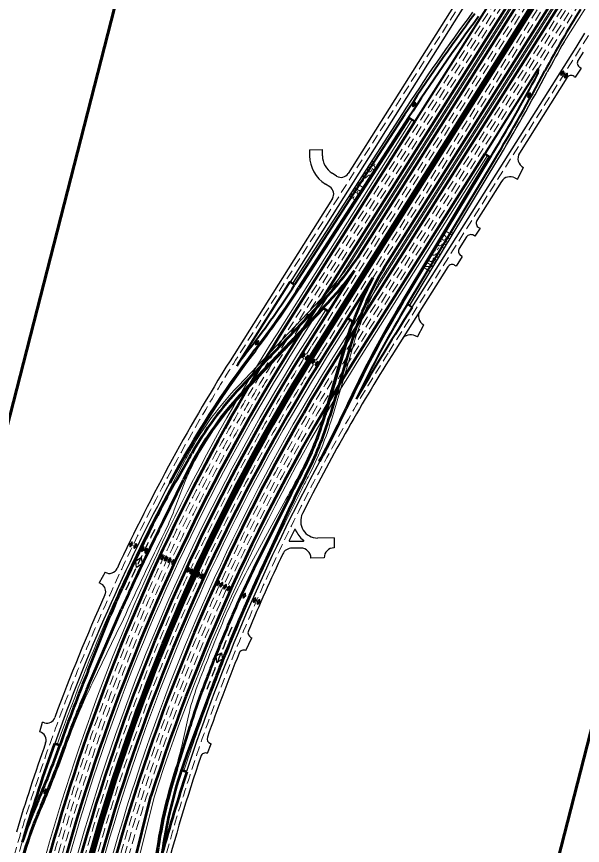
# Model space of a CAD drawing. Extents: x 2329387 to 2347382, y 6951580 to 6987999.
# Drawn here: x 2330678 to 2332354, y 6976295 to 6978752 of the extents above; entities that cross this region are included whole.
import ezdxf

# ---------------------------------------------------------------- set-up
doc = ezdxf.new("R2010")
doc.units = 0
doc.header["$LTSCALE"] = 9.6
doc.linetypes.add('MEDIUM_DASHED', pattern=[4.5, 3, -1.5])
for name, color, linetype, lineweight in [('26', 7, 'Continuous', 53), ('27', 7, 'Continuous', 40), ('28', 7, 'Continuous', 25), ('30', 7, 'Continuous', 13), ('31', 7, 'Continuous', 53), ('41', 7, 'Continuous', 35), ('50', 7, 'MEDIUM_DASHED', 13), ('62', 7, 'Continuous', 60), ('8', 7, 'Continuous', 25)]:
    doc.layers.add(name, color=color, linetype=linetype, lineweight=lineweight)
doc.layers.add('40', color=7, linetype='Continuous')

msp = doc.modelspace()

# ---------------------------------------------------------------- linework, layer by layer
at = {"layer": '26'}
for p, q in [((2332311.656, 6979070.557), (2331498.365, 6977780.703)), ((2332421.635, 6979001.242), (2331638.131, 6977758.629)), ((2331857.752, 6978440.676), (2331457.762, 6977806.304)), ((2332064.627, 6978345.043), (2331678.734, 6977733.028)), ((2331002.95, 6976149.883), (2331075.736, 6976441.452))]:
    msp.add_line(p, q, dxfattribs=at)
at = {"layer": '26', "lineweight": 13}
for p, q in [((2332320.115, 6979065.224), (2331506.824, 6977775.369)), ((2332413.166, 6979006.559), (2331629.672, 6977763.963)), ((2332480.843, 6978963.9), (2332299.878, 6978676.896)), ((2331849.293, 6978446.009), (2331449.303, 6977811.638)), ((2332073.086, 6978339.709), (2331687.192, 6977727.694)), ((2331012.618, 6976147.33), (2331085.256, 6976438.392))]:
    msp.add_line(p, q, dxfattribs=at)
for centre, radius, end in [((2336379.635, 6974702.917), 5828.578, 173.81243), ((2336379.635, 6974702.917), 5760.578, 175.11878), ((2336484.72, 6974702.711), 5739.578, 175.08526), ((2336484.72, 6974702.711), 5671.578, 162.17978)]:
    msp.add_arc(centre, radius, 147.76736, end, dxfattribs=at)
at = {"layer": '26'}
for centre, radius, end in [((2336379.635, 6974702.917), 5818.578, 172.95165), ((2336379.635, 6974702.917), 5770.578, 175.12833), ((2336484.72, 6974702.711), 5729.578, 175.07558), ((2336484.72, 6974702.711), 5681.578, 162.17978)]:
    msp.add_arc(centre, radius, 147.76736, end, dxfattribs=at)
at = {"layer": '27'}
for p, q in [((2332110.036, 6978840.79), (2331857.752, 6978440.676)), ((2332223.361, 6978596.79), (2332064.627, 6978345.043)), ((2332223.361, 6978596.79), (2332222.374, 6978582.1)), ((2331827.389, 6978460.014), (2331501.466, 6977956.236)), ((2331839.144, 6978452.409), (2331513.22, 6977948.632)), ((2331857.752, 6978440.676), (2331839.143, 6978452.41)), ((2331823.332, 6977906.104), (2332081.553, 6978334.383)), ((2332081.547, 6978334.374), (2332064.627, 6978345.043)), ((2331835.322, 6977898.876), (2332093.542, 6978327.154)), ((2331487.041, 6977965.235), (2331343.214, 6977737.129)), ((2331501.421, 6977956.168), (2331487.041, 6977965.235)), ((2331835.322, 6977898.876), (2331849.702, 6977889.808)), ((2331849.702, 6977889.808), (2331826.155, 6977852.463))]:
    msp.add_line(p, q, dxfattribs=at)
at = {"layer": '27', "lineweight": 25}
for p, q in [((2331820.672, 6978464.359), (2331494.654, 6977960.435)), ((2331842.502, 6978450.236), (2331516.579, 6977946.459)), ((2331819.907, 6977908.17), (2332078.163, 6978336.508)), ((2331842.09, 6977894.608), (2332100.393, 6978323.023)), ((2331577.072, 6977433.381), (2331573.552, 6977435.281)), ((2331130.648, 6977370.742), (2331134.18, 6977368.863))]:
    msp.add_line(p, q, dxfattribs=at)
for centre, radius, start, end in [((2336637.99, 6975347.75), 5737.578, 143.44999, 147.09877), ((2334771.719, 6977244.678), 2856.789, 149.91143, 151.98091), ((2327184.689, 6981282.018), 5737.578, 328.95434, 331.98091), ((2329096.165, 6979512.368), 2882.789, 322.59517, 327.09877), ((2334639.165, 6976208.364), 3292.044, 148.91312, 155.15778), ((2333647.533, 6976031.977), 2846.789, 142.59517, 151.99089), ((2329068.37, 6978787.417), 2846.789, 331.64269, 335.15778)]:
    msp.add_arc(centre, radius, start, end, dxfattribs=at)
at = {"layer": '27'}
for centre, radius, start, end in [((2336637.99, 6975347.75), 5729.578, 143.44999, 147.09877), ((2336637.99, 6975347.75), 5715.578, 143.44999, 147.09877), ((2334771.719, 6977244.678), 2864.789, 147.76736, 151.98091), ((2327184.689, 6981282.018), 5715.578, 328.95434, 331.81118), ((2327184.689, 6981282.018), 5729.578, 328.95434, 331.98091), ((2329096.165, 6979512.368), 2864.789, 322.59517, 327.09878), ((2329096.165, 6979512.368), 2878.789, 322.59517, 327.09877), ((2334639.165, 6976208.364), 3288.044, 148.91312, 155.15778), ((2334639.165, 6976208.364), 3274.044, 148.91312, 154.49671), ((2338308.575, 6973765.105), 7663.437, 147.76735, 149.81661), ((2333647.533, 6976031.977), 2864.789, 142.59517, 144.00072), ((2333647.533, 6976031.977), 2850.789, 142.59517, 151.99089), ((2336205.029, 6974671.61), 5747.578, 147.76736, 148.01803), ((2329068.37, 6978787.417), 2850.789, 331.64269, 335.15778)]:
    msp.add_arc(centre, radius, start, end, dxfattribs=at)
at = {"layer": '28'}
for p, q in [((2332268.48, 6979251.445), (2331660.223, 6978286.769)), ((2332225.857, 6979135.099), (2331487.887, 6977964.701)), ((2332360.201, 6978702.494), (2332334.063, 6978659.865)), ((2332334.063, 6978659.865), (2331848.856, 6977890.342)), ((2332356.056, 6978645.998), (2332341.081, 6978622.248)), ((2332308.053, 6978569.867), (2332167.564, 6978347.055)), ((2332329.047, 6978574.357), (2332332.909, 6978571.789)), ((2331545.827, 6978357.015), (2331583.827, 6978357.205)), ((2331545.827, 6978357.015), (2331545.917, 6978339.029)), ((2331583.92, 6978338.547), (2331583.827, 6978357.205)), ((2331625.742, 6978278.955), (2331612.847, 6978287.086)), ((2332161.923, 6978269.542), (2332179.767, 6978304.102)), ((2332114.627, 6978263.098), (2332041.55, 6978147.201)), ((2332153.767, 6978273.753), (2332161.923, 6978269.542)), ((2331605.474, 6978246.812), (2331592.58, 6978254.942)), ((2331613.288, 6978212.33), (2331322.066, 6977750.463)), ((2332050.692, 6978124.201), (2332035.634, 6978100.319)), ((2332050.692, 6978124.201), (2332047.522, 6978125.789)), ((2332010.796, 6978098.425), (2331989.138, 6978064.077)), ((2332035.634, 6978100.319), (2332031.881, 6978102.854)), ((2331997.916, 6978040.5), (2331993.218, 6978043.793)), ((2331955.002, 6978009.939), (2331789.547, 6977747.531)), ((2331865.02, 6977802.141), (2331883.823, 6977837.753)), ((2331865.02, 6977802.141), (2331858.956, 6977805.343)), ((2331618.535, 6977206.483), (2331569.576, 6977206.193)), ((2331618.535, 6977206.483), (2331618.708, 6977177.234)), ((2331526.484, 6977196.296), (2331487.168, 6977196.194)), ((2331519.723, 6977176.278), (2331493.255, 6977176.209)), ((2331588.788, 6977147.607), (2331549.8, 6977146.362)), ((2330940.545, 6977104.625), (2330922.891, 6977073.251)), ((2330929.109, 6977069.752), (2330922.891, 6977073.251)), ((2331357.18, 6976872.848), (2331374.184, 6976910.605)), ((2331372.097, 6976911.544), (2331374.184, 6976910.605)), ((2330746.713, 6976631.731), (2330754.247, 6976660.161)), ((2330760.898, 6976658.378), (2330754.247, 6976660.161)), ((2331243.387, 6976568.227), (2331254.398, 6976595.868)), ((2331251.762, 6976596.918), (2331254.398, 6976595.868))]:
    msp.add_line(p, q, dxfattribs=at)
for points in [[(2332346.54, 6978601.104), (2332350.144, 6978599.122), (2332332.909, 6978571.789)], [(2331997.916, 6978040.5), (2331979.8, 6978011.769), (2331976.3, 6978014.222)]]:
    msp.add_lwpolyline(points, dxfattribs=at)
for centre, radius, start, end in [((2332353.769, 6978614.247), 15, 147.76735, 241.1848), ((2332320.742, 6978561.866), 15, 56.37914, 147.76735), ((2331645.916, 6978339.531), 100, 180.28727, 237.76736), ((2331645.916, 6978339.531), 62, 180.28727, 237.76652), ((2332192.941, 6978331.055), 30, 147.76735, 243.95256), ((2331639.076, 6978300.103), 25, 237.76736, 327.76736), ((2332140.003, 6978247.097), 30, 62.69027, 147.76736), ((2331592.14, 6978225.664), 25, 327.76736, 57.76736), ((2332054.239, 6978139.201), 15, 147.76735, 243.3983), ((2332023.484, 6978090.425), 15, 55.95931, 147.76735), ((2332001.827, 6978056.077), 15, 147.76736, 234.97513), ((2331967.691, 6978001.938), 15, 54.97512, 147.76735), ((2331898.424, 6977863.96), 30, 147.76735, 240.87564), ((2331844.949, 6977778.813), 30, 62.16612, 148.16102), ((2336205.029, 6974671.61), 5772.578, 147.76736, 154.9494), ((2336512.636, 6974769.483), 5583.578, 147.76735, 153.29574), ((2336512.636, 6974769.483), 5609.578, 151.64269, 161.88221), ((2336205.029, 6974671.61), 5746.578, 151.99089, 160.42487), ((2331569.28, 6977256.192), 50, 153.29574, 270.33911), ((2336512.636, 6974769.483), 5583.578, 153.84901, 154.20645), ((2331502.412, 6977229.497), 2, 21.76266, 153.84901), ((2331569.28, 6977256.192), 70, 201.76266, 233.52533), ((2331487.163, 6977198.194), 2, 154.20645, 270.14866), ((2331526.479, 6977198.296), 2, 270.14866, 53.52533), ((2336512.636, 6974769.483), 5583.578, 154.66164, 157.22424), ((2331493.333, 6977146.209), 30, 90.14866, 154.66164), ((2331519.8, 6977146.278), 30, 0.16043, 90.14866), ((2331618.786, 6977147.234), 30, 90.14866, 179.28828), ((2330952.805, 6977126.412), 25, 240.63342, 334.9494), ((2330916.849, 6977047.964), 25, 335.80224, 60.63342), ((2336205.029, 6974671.61), 5772.578, 155.80224, 159.70496), ((2331378.256, 6976925.222), 15, 157.22424, 245.75634), ((2336512.636, 6974769.483), 5583.578, 157.95936, 160.69046), ((2331351.021, 6976859.171), 15, 65.75634, 157.95936), ((2330767.371, 6976682.526), 25, 254.9952, 339.70496), ((2330740.24, 6976607.583), 25, 340.49264, 74.9952), ((2331257.313, 6976610.853), 15, 160.69046, 248.27984), ((2336205.029, 6974671.61), 5772.578, 160.49264, 163.25319), ((2331237.836, 6976554.292), 15, 68.27984, 161.30596), ((2336512.636, 6974769.483), 5583.578, 161.30596, 169.12563)]:
    msp.add_arc(centre, radius, start, end, dxfattribs=at)
at = {"layer": '30', "lineweight": 53}
for p, q in [((2332362.418, 6979038.57), (2331562.066, 6977769.236)), ((2332370.877, 6979033.236), (2331570.526, 6977763.904)), ((2331601.848, 6977877.327), (2331541.757, 6977782.025)), ((2331657.84, 6977857.384), (2331590.832, 6977751.111))]:
    msp.add_line(p, q, dxfattribs=at)
at = {"layer": '30'}
for p, q in [((2332365.802, 6979036.436), (2331565.442, 6977767.091)), ((2332367.494, 6979035.37), (2331567.134, 6977766.025)), ((2331593.389, 6977882.66), (2331533.298, 6977787.359)), ((2331666.299, 6977852.05), (2331599.291, 6977745.777))]:
    msp.add_line(p, q, dxfattribs=at)
for radius, start, end in [(5768.578, 147.76736, 175.19992), (5730.578, 147.76724, 175.16391), (5728.578, 147.76736, 175.16201), (5690.578, 147.76711, 175.12549)]:
    msp.add_arc((2336412.878, 6974710.64), radius, start, end, dxfattribs=at)
at = {"layer": '30', "lineweight": 53}
for radius, start, end in [(5758.578, 147.76736, 175.19049), (5734.578, 147.76724, 175.16773), (5724.578, 147.76721, 175.15818), (5700.578, 147.76711, 175.13515)]:
    msp.add_arc((2336412.878, 6974710.64), radius, start, end, dxfattribs=at)
at = {"layer": '31', "lineweight": 13}
for p, q in [((2332323.507, 6979063.104), (2331660.215, 6978011.144)), ((2332409.788, 6979008.702), (2331753.141, 6977967.28)), ((2331334.09, 6977656.656), (2331579.235, 6977913.908)), ((2331352.918, 6977638.725), (2331588.381, 6977885.818)), ((2331651.521, 6977788.701), (2331588.214, 6977572.468)), ((2331676.474, 6977781.395), (2331613.166, 6977565.163)), ((2331176.197, 6977435.62), (2331104.254, 6977300.037)), ((2331494.023, 6977294.11), (2331523.686, 6977353.276)), ((2331144.723, 6977289.315), (2331166.904, 6977349.026)), ((2331475.72, 6977320.3), (2331373.595, 6977133.482)), ((2330976.4, 6977036.426), (2330983.078, 6977051.188)), ((2330903.572, 6976778.893), (2330973.095, 6976922.285)), ((2331170.446, 6976603.64), (2331187.035, 6976679.271)), ((2331183.079, 6976545.416), (2331173.582, 6976516.39))]:
    msp.add_line(p, q, dxfattribs=at)
at = {"layer": '31'}
for p, q in [((2332331.966, 6979057.771), (2331701.482, 6978057.842)), ((2332401.329, 6979014.035), (2331777.49, 6978024.646)), ((2331678.445, 6977998.808), (2331601.848, 6977877.327)), ((2331733.384, 6977977.193), (2331657.84, 6977857.384)), ((2331339.882, 6977651.137), (2331585.026, 6977908.389)), ((2331350.017, 6977641.479), (2331595.161, 6977898.731)), ((2331584.93, 6977887.994), (2331601.848, 6977877.327)), ((2331674.758, 6977846.716), (2331657.84, 6977857.384)), ((2331655.36, 6977787.577), (2331592.052, 6977571.344)), ((2331668.796, 6977783.643), (2331605.488, 6977567.411)), ((2331153.057, 6977380.215), (2331187.402, 6977440.129)), ((2331112.877, 6977256.989), (2331172.117, 6977379.03)), ((2331490.262, 6977336.055), (2331380.805, 6977115.462)), ((2331490.438, 6977302.682), (2331411.832, 6977132.699)), ((2330890.021, 6976767.432), (2330988.98, 6976995.492)), ((2330889.998, 6976814.028), (2330955.406, 6976976.294)), ((2331248.342, 6976741.626), (2331182.007, 6976564.575)), ((2331162.899, 6976555.449), (2331191.7, 6976649.047)), ((2330805.661, 6976591.598), (2330789.644, 6976597.293)), ((2331165.979, 6976518.878), (2331182.136, 6976513.592))]:
    msp.add_line(p, q, dxfattribs=at)
for centre, radius, start, end in [((2330893.717, 6978567.162), 954.93, 316.38051, 327.76736), ((2332585.255, 6977515.326), 954.93, 147.76736, 163.68126), ((2330893.717, 6978567.162), 968.93, 316.38051, 324.08538), ((2332585.255, 6977515.326), 968.93, 151.53473, 163.68126), ((2332031.192, 6976992.365), 954.93, 136.38063, 150.92486), ((2332031.192, 6976992.365), 940.93, 136.38062, 150.92488), ((2330689.03, 6977835.727), 940.93, 332.23231, 343.68126), ((2330689.03, 6977835.727), 954.93, 332.23231, 343.68126), ((2332460.724, 6976753.535), 1432.395, 150.92488, 154.10787), ((2329944.711, 6978152.5), 1432.395, 330.17657, 330.92487), ((2333638.437, 6975955.47), 2864.789, 150.17651, 153.42487), ((2334056.496, 6976062.689), 2864.789, 152.23231, 153.60939), ((2333223.92, 6976501.057), 1909.859, 152.23231, 155.18246), ((2328535.662, 6978507.98), 2864.789, 333.42487, 334.10787), ((2336205.029, 6974671.61), 5734.578, 153.42487, 155.42487), ((2336205.029, 6974671.61), 5710.578, 153.42487, 155.42488), ((2336612.278, 6974727.825), 5729.578, 155.18247, 157.31121), ((2333947.042, 6975842.105), 2864.789, 153.60956, 157.31121), ((2332726.766, 6976262.257), 1909.859, 155.42487, 158.04561), ((2333617.021, 6975855.134), 2864.789, 155.42488, 156.54305), ((2336512.636, 6974769.483), 5645.578, 157.31121, 159.34281), ((2336512.636, 6974769.483), 5621.578, 157.31121, 159.34281), ((2336204.087, 6974671.945), 5729.578, 158.04588, 160.42487), ((2333518.065, 6975627.081), 2864.789, 156.54319, 160.42487), ((2333017.095, 6976087.355), 1909.859, 159.34281, 162.89632), ((2336613.692, 6974731.383), 5729.578, 159.34281, 159.46047), ((2336205.029, 6974671.61), 5747.578, 160.42487, 163.25319), ((2328106.449, 6977551.424), 2864.789, 336.71372, 340.42487), ((2328106.449, 6977551.424), 2878.789, 336.71372, 340.42487), ((2332255.113, 6976162.52), 1145.952, 159.46081, 161.8822), ((2329337.506, 6977117.144), 1909.859, 341.88219, 342.89626), ((2332527.354, 6976073.444), 1446.395, 161.8822, 172.82234), ((2332527.354, 6976073.444), 1432.395, 161.8822, 172.11257), ((2336512.636, 6974769.483), 5608.578, 161.88221, 164.48201), ((2332053.588, 6975852.637), 1432.395, 156.71372, 161.60692), ((2332053.588, 6975852.637), 1418.395, 156.71372, 165.90574), ((2333421.525, 6975509.181), 2840.789, 163.25319, 163.73969)]:
    msp.add_arc(centre, radius, start, end, dxfattribs=at)
at = {"layer": '31', "lineweight": 13}
for centre, radius, start, end in [((2330893.717, 6978567.162), 946.93, 316.38051, 324.04284), ((2332585.255, 6977515.326), 946.93, 151.49187, 163.68126), ((2332585.255, 6977515.326), 972.93, 159.94915, 163.68126), ((2332031.192, 6976992.365), 962.93, 136.38066, 150.92486), ((2332031.192, 6976992.365), 936.93, 136.38016, 150.92486), ((2330689.03, 6977835.727), 936.93, 332.23231, 343.68126), ((2330689.03, 6977835.727), 962.93, 332.23231, 343.68126), ((2332441.497, 6976764.226), 1432.395, 150.92486, 152.04864), ((2331838.276, 6977099.631), 716.197, 150.92486, 159.62148), ((2326448.284, 6980068.564), 5729.578, 331.33664, 332.23231), ((2333230.999, 6976497.33), 1909.859, 152.23229, 153.37349), ((2333634.86, 6975957.26), 2864.789, 152.04892, 153.42487), ((2330473.35, 6977538.709), 716.197, 333.42487, 339.62148), ((2336615.969, 6974726.282), 5729.578, 153.37363, 157.31121), ((2336205.029, 6974671.61), 5738.578, 153.42487, 155.42487), ((2336205.029, 6974671.61), 5692.578, 153.42487, 155.42487), ((2333049.404, 6976217.389), 1909.859, 151.33644, 157.31121), ((2332723.128, 6976263.921), 1909.859, 155.42487, 155.65614), ((2336196.549, 6974674.625), 5729.578, 155.65614, 160.42487), ((2325817.529, 6979421.925), 5729.578, 334.13389, 335.42487), ((2336512.636, 6974769.483), 5663.578, 157.31121, 159.34281), ((2336512.636, 6974769.483), 5617.578, 157.31121, 159.34281), ((2332622.096, 6975945.683), 1909.859, 154.13401, 160.42488), ((2331808.872, 6976542.873), 636.62, 159.34281, 167.62824), ((2336617.435, 6974729.972), 5729.578, 159.34281, 161.52719), ((2330370.942, 6976779.009), 818.511, 341.8822, 347.62824), ((2328106.449, 6977551.424), 2882.789, 336.71372, 340.42487), ((2332527.354, 6976073.444), 1450.395, 161.8822, 172.82234), ((2332053.588, 6975852.637), 1414.395, 156.71372, 165.90574)]:
    msp.add_arc(centre, radius, start, end, dxfattribs=at)
at = {"layer": '31', "linetype": 'MEDIUM_DASHED', "lineweight": 25}
for centre, radius, start, end in [((2336205.029, 6974671.61), 5722.578, 153.42487, 155.42487), ((2336512.636, 6974769.483), 5633.578, 157.31121, 159.34281)]:
    msp.add_arc(centre, radius, start, end, dxfattribs=at)
at = {"layer": '41'}
for points in [[(2332289.115, 6978578.974), (2332291.667, 6978577.395), (2332295.248, 6978583.183), (2332297.32, 6978581.901), (2332297.895, 6978590.012), (2332290.893, 6978585.877), (2332292.696, 6978584.762)], [(2332300.338, 6978571.952), (2332302.89, 6978570.374), (2332306.471, 6978576.162), (2332308.544, 6978574.88), (2332309.118, 6978582.991), (2332302.117, 6978578.856), (2332303.919, 6978577.741)], [(2332191.406, 6978513.396), (2332194.081, 6978512.037), (2332197.165, 6978518.105), (2332199.337, 6978517.001), (2332199.231, 6978525.132), (2332192.6, 6978520.425), (2332194.489, 6978519.465)], [(2331860.686, 6978495.766), (2331858.146, 6978497.364), (2331854.523, 6978491.601), (2331852.46, 6978492.898), (2331851.826, 6978484.792), (2331858.858, 6978488.876), (2331857.064, 6978490.004)], [(2331395.615, 6977789.206), (2331393.232, 6977791.031), (2331389.093, 6977785.627), (2331387.158, 6977787.109), (2331385.78, 6977779.096), (2331393.158, 6977782.514), (2331391.475, 6977783.802)], [(2331532.283, 6977752.201), (2331529.731, 6977753.78), (2331526.15, 6977747.991), (2331524.077, 6977749.274), (2331523.502, 6977741.162), (2331530.504, 6977745.297), (2331528.701, 6977746.413)], [(2331542.873, 6977745.888), (2331540.321, 6977747.467), (2331536.74, 6977741.678), (2331534.667, 6977742.96), (2331534.092, 6977734.849), (2331541.094, 6977738.984), (2331539.292, 6977740.099)], [(2331552.222, 6977724.501), (2331554.774, 6977722.922), (2331558.355, 6977728.711), (2331560.427, 6977727.428), (2331561.002, 6977735.539), (2331554, 6977731.404), (2331555.803, 6977730.289)], [(2331562.365, 6977718.264), (2331564.917, 6977716.685), (2331568.498, 6977722.474), (2331570.571, 6977721.191), (2331571.145, 6977729.303), (2331564.144, 6977725.168), (2331565.946, 6977724.052)], [(2331021.472, 6977192.902), (2331018.746, 6977194.158), (2331015.898, 6977187.976), (2331013.684, 6977188.996), (2331014.103, 6977180.875), (2331020.548, 6977185.833), (2331018.623, 6977186.72)], [(2331033.539, 6977188.037), (2331030.813, 6977189.293), (2331027.965, 6977183.111), (2331025.751, 6977184.131), (2331026.17, 6977176.01), (2331032.615, 6977180.968), (2331030.69, 6977181.855)], [(2331055.572, 6977178.351), (2331052.847, 6977179.607), (2331049.998, 6977173.425), (2331047.785, 6977174.445), (2331048.204, 6977166.324), (2331054.649, 6977171.282), (2331052.724, 6977172.169)], [(2331066.089, 6977173.581), (2331063.364, 6977174.837), (2331060.515, 6977168.655), (2331058.301, 6977169.675), (2331058.72, 6977161.554), (2331065.165, 6977166.512), (2331063.24, 6977167.399)], [(2331113.232, 6977154.7), (2331110.507, 6977155.956), (2331107.659, 6977149.774), (2331105.445, 6977150.794), (2331105.864, 6977142.673), (2331112.309, 6977147.631), (2331110.384, 6977148.518)], [(2331123.368, 6977150.824), (2331120.643, 6977152.08), (2331117.794, 6977145.898), (2331115.581, 6977146.918), (2331116, 6977138.797), (2331122.445, 6977143.755), (2331120.52, 6977144.642)], [(2331134.67, 6977145.756), (2331131.945, 6977147.012), (2331129.097, 6977140.83), (2331126.883, 6977141.85), (2331127.302, 6977133.729), (2331133.747, 6977138.687), (2331131.822, 6977139.574)], [(2331145.632, 6977140.596), (2331142.907, 6977141.852), (2331140.058, 6977135.67), (2331137.845, 6977136.69), (2331138.263, 6977128.569), (2331144.709, 6977133.527), (2331142.784, 6977134.414)], [(2331189.532, 6977117.116), (2331186.807, 6977118.372), (2331183.958, 6977112.19), (2331181.745, 6977113.21), (2331182.164, 6977105.089), (2331188.609, 6977110.047), (2331186.684, 6977110.934)], [(2331199.772, 6977112.48), (2331197.046, 6977113.735), (2331194.198, 6977107.553), (2331191.984, 6977108.573), (2331192.403, 6977100.453), (2331198.848, 6977105.411), (2331196.923, 6977106.298)], [(2331211.658, 6977092.392), (2331214.384, 6977091.136), (2331217.232, 6977097.318), (2331219.446, 6977096.298), (2331219.027, 6977104.419), (2331212.582, 6977099.461), (2331214.507, 6977098.574)], [(2331222.487, 6977087.439), (2331225.212, 6977086.183), (2331228.061, 6977092.365), (2331230.274, 6977091.345), (2331229.856, 6977099.465), (2331223.41, 6977094.508), (2331225.335, 6977093.621)], [(2331270.151, 6977066.995), (2331272.876, 6977065.739), (2331275.724, 6977071.921), (2331277.938, 6977070.901), (2331277.519, 6977079.022), (2331271.074, 6977074.064), (2331272.999, 6977073.177)], [(2331279.961, 6977062.418), (2331282.686, 6977061.162), (2331285.535, 6977067.344), (2331287.748, 6977066.324), (2331287.33, 6977074.445), (2331280.885, 6977069.487), (2331282.81, 6977068.6)], [(2331290.783, 6977056.781), (2331293.508, 6977055.525), (2331296.356, 6977061.707), (2331298.57, 6977060.687), (2331298.151, 6977068.808), (2331291.706, 6977063.85), (2331293.631, 6977062.963)], [(2331301.024, 6977051.8), (2331303.75, 6977050.544), (2331306.598, 6977056.726), (2331308.812, 6977055.706), (2331308.393, 6977063.827), (2331301.948, 6977058.869), (2331303.873, 6977057.982)], [(2331347.994, 6977029.93), (2331350.719, 6977028.674), (2331353.568, 6977034.856), (2331355.781, 6977033.836), (2331355.363, 6977041.957), (2331348.917, 6977036.999), (2331350.842, 6977036.112)], [(2331378.28, 6977016.811), (2331381.006, 6977015.555), (2331383.854, 6977021.737), (2331386.068, 6977020.717), (2331385.649, 6977028.838), (2331379.204, 6977023.88), (2331381.129, 6977022.993)], [(2331390.491, 6977011.56), (2331393.217, 6977010.304), (2331396.065, 6977016.486), (2331398.279, 6977015.466), (2331397.86, 6977023.587), (2331391.415, 6977018.629), (2331393.34, 6977017.742)], [(2330766.614, 6976461.245), (2330763.855, 6976462.424), (2330761.18, 6976456.165), (2330758.939, 6976457.122), (2330759.585, 6976449.017), (2330765.889, 6976454.153), (2330763.94, 6976454.986)]]:
    msp.add_lwpolyline(points, close=True, dxfattribs=at)
at = {"layer": '50'}
for p, q in [((2332277.122, 6979240.776), (2331333.063, 6977743.529)), ((2332281.204, 6979089.757), (2331467.913, 6977799.904)), ((2332291.355, 6979083.358), (2331478.063, 6977793.503)), ((2332301.506, 6979076.958), (2331488.214, 6977787.103)), ((2332342.117, 6979051.37), (2331678.445, 6977998.808)), ((2332352.268, 6979044.97), (2331551.912, 6977775.631)), ((2332381.028, 6979026.836), (2331580.679, 6977757.508)), ((2332391.179, 6979020.436), (2331733.384, 6977977.193)), ((2332431.778, 6978994.829), (2331648.282, 6977752.229)), ((2332441.937, 6978988.442), (2331658.432, 6977745.828)), ((2332452.079, 6978982.028), (2331668.583, 6977739.428)), ((2332462.231, 6978975.63), (2332223.361, 6978596.79)), ((2332371.57, 6978694.976), (2331778.55, 6977754.465))]:
    msp.add_line(p, q, dxfattribs=at)
for centre, radius, start, end in [((2336379.635, 6974702.917), 5806.578, 147.76736, 175.15429), ((2336379.635, 6974702.917), 5794.578, 147.76736, 175.15112), ((2336379.635, 6974702.917), 5782.578, 147.76736, 175.13975), ((2336412.878, 6974710.64), 5746.578, 147.76728, 175.18607), ((2336205.029, 6974671.61), 5759.578, 147.76736, 163.25319), ((2336412.878, 6974710.64), 5712.578, 147.76716, 175.15256), ((2336484.72, 6974702.711), 5717.578, 147.76736, 175.06392), ((2336484.72, 6974702.711), 5705.578, 147.76736, 175.05221), ((2336512.636, 6974769.483), 5596.578, 147.76735, 169.12563), ((2336484.72, 6974702.711), 5693.578, 147.76736, 175.04045), ((2333421.525, 6975509.181), 2852.789, 163.25319, 175.63273), ((2333421.525, 6975509.181), 2840.789, 163.73969, 175.63273)]:
    msp.add_arc(centre, radius, start, end, dxfattribs=at)
at = {"layer": '62'}
msp.add_lwpolyline([(2333194.662, 6979814.447), (2331455.123, 6973029.722), (2329419.111, 6972738.941), (2331377.669, 6980377.903)], close=True, dxfattribs=at)
at = {"layer": '8'}
for points in [[(2331047.098, 6977148.27), (2331049.384, 6977129.309), (2331032.681, 6977119.329), (2331030.584, 6977138.666)], [(2331285.162, 6976866.394), (2331287.448, 6976847.433), (2331270.745, 6976837.453), (2331268.648, 6976856.79)]]:
    msp.add_lwpolyline(points, close=True, dxfattribs=at)

# ---------------------------------------------------------------- texts
at = {"layer": '40'}
for s, rotation, width, p in [('35S-183', 237.231, 1.1, (2331733.408, 6978327.289)), ('183-35N', 237.862, 1.15, (2331954.355, 6978125.514))]:
    msp.add_text(s, height=24, rotation=rotation, dxfattribs=dict(at, width=width)).set_placement(p)

doc.saveas('drawing.dxf')
